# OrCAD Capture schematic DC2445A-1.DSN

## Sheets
1 PAGE 2: size Custom; title: BAR GRAPH FOR 400mA WIRELESS SYNCHRONOUS; rev: 1; note: DEMO CIRCUIT 2445A - A / B
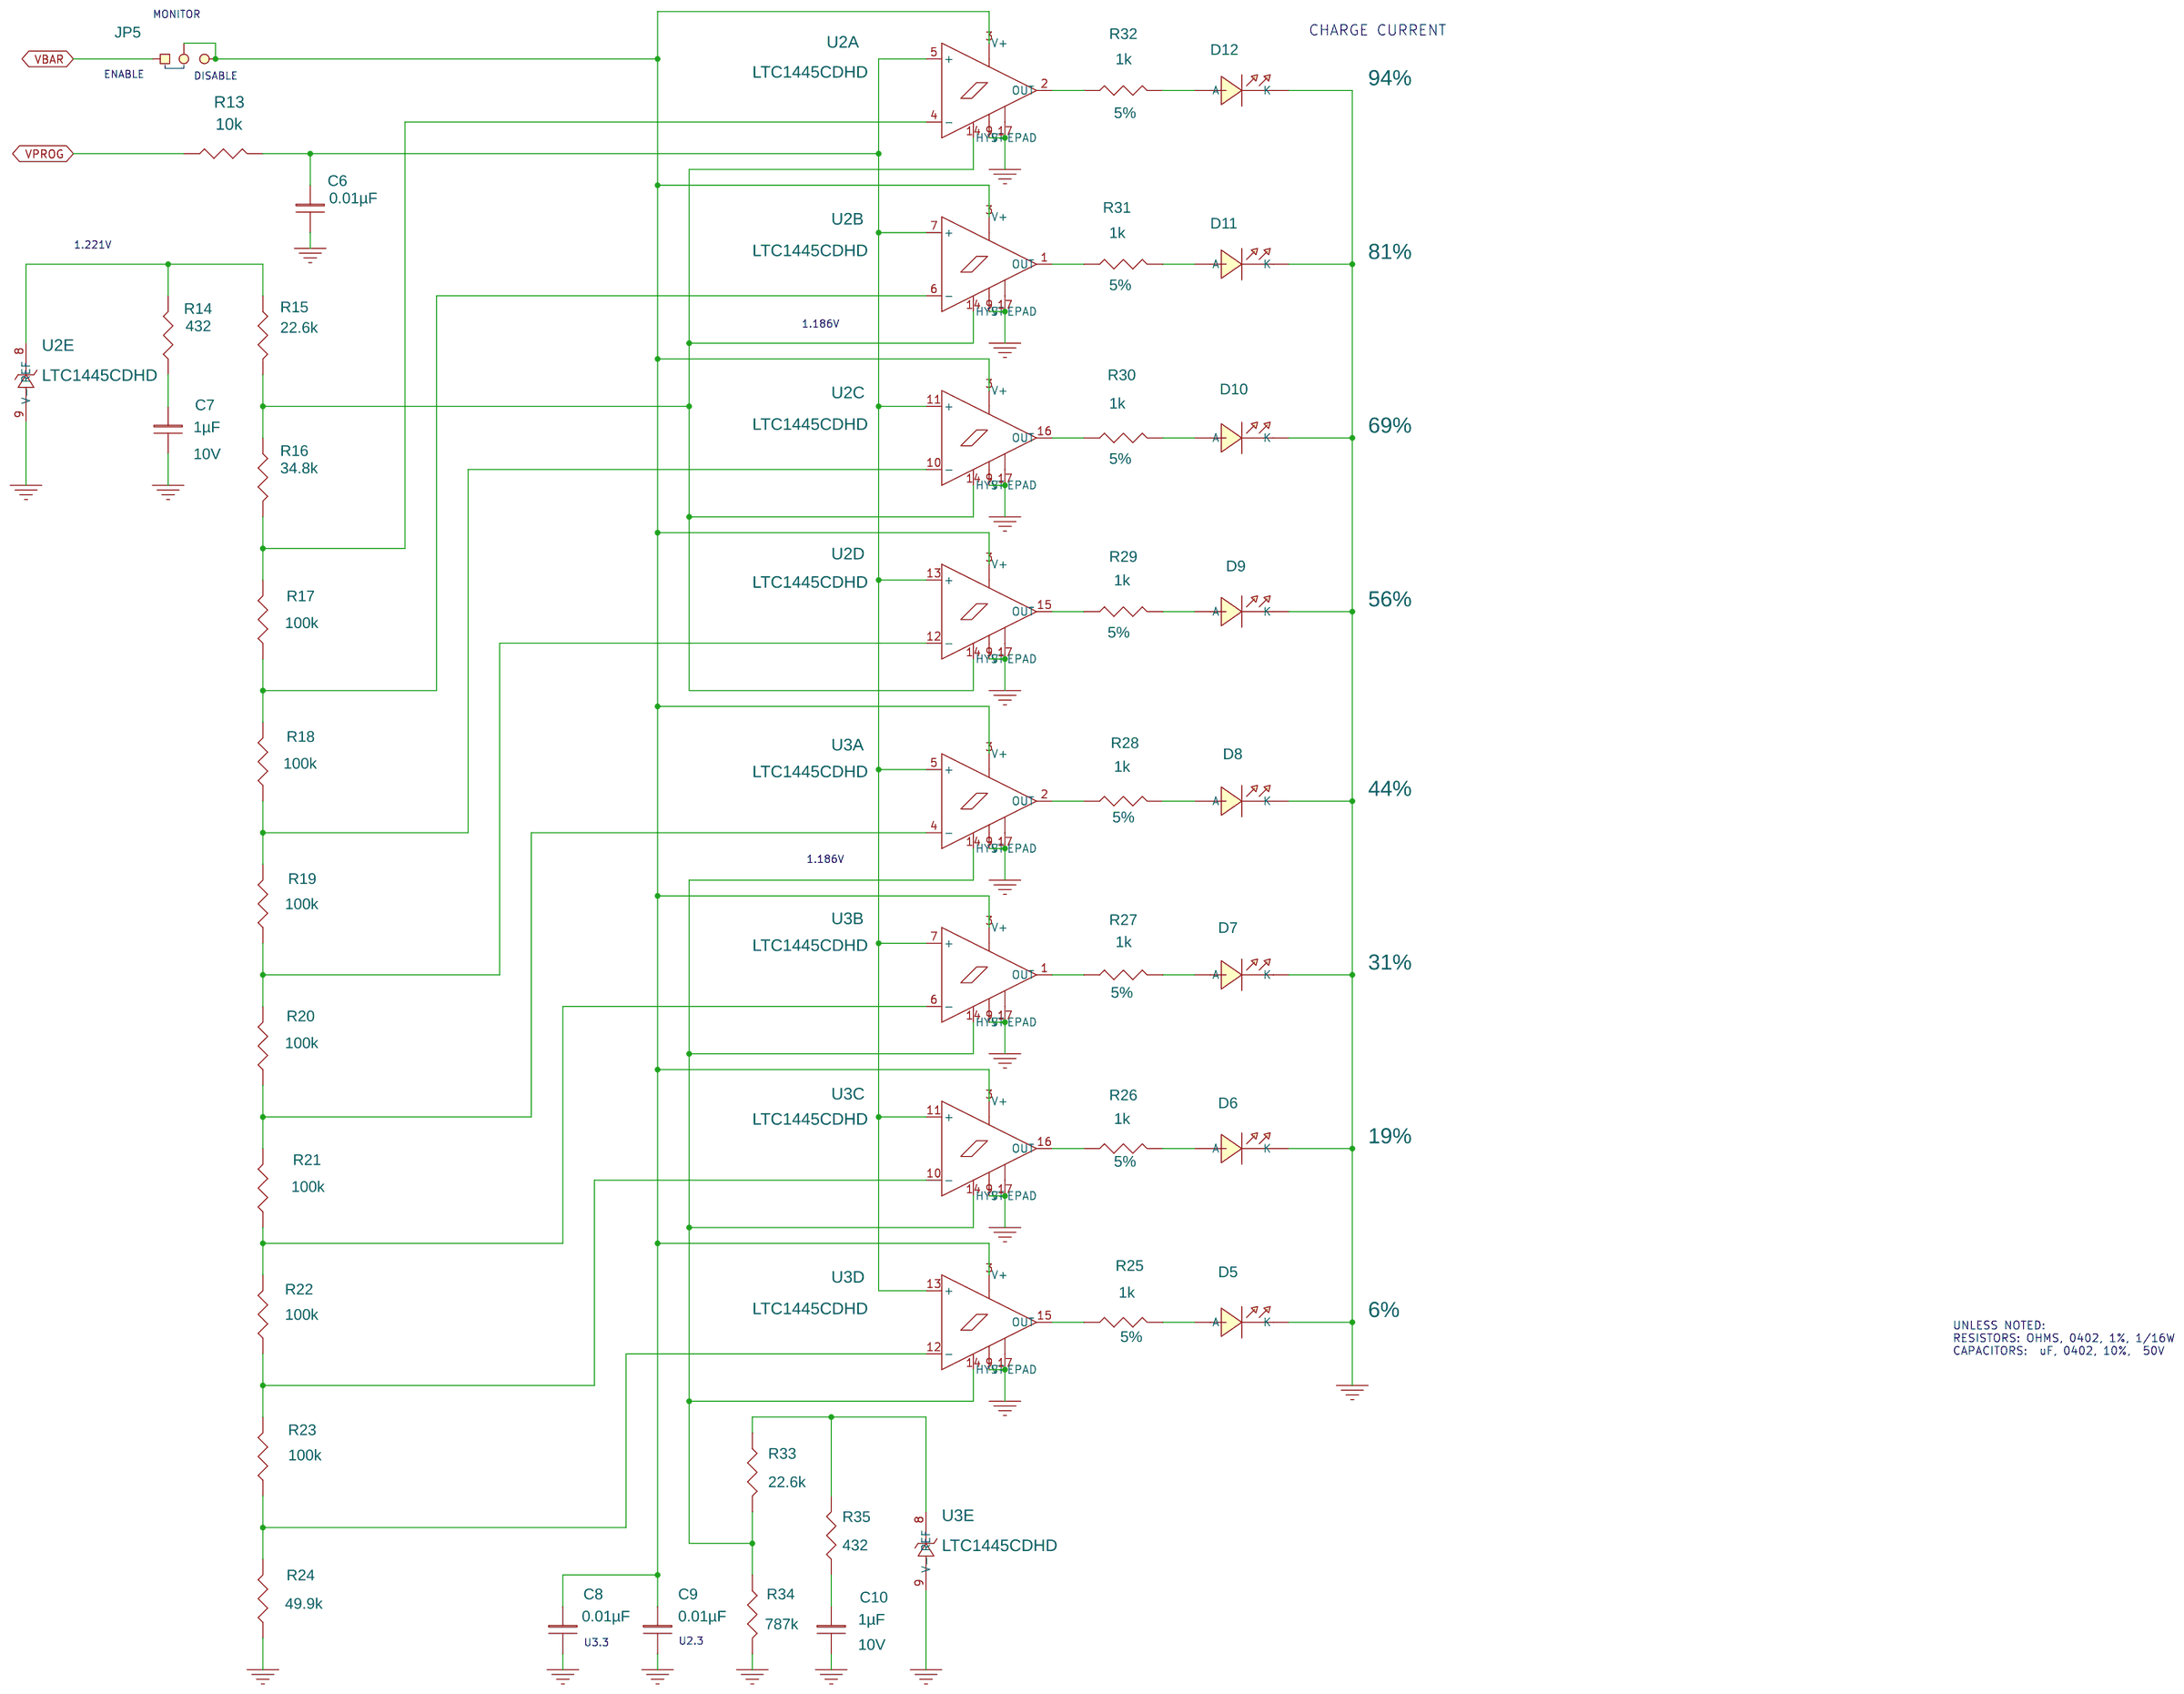
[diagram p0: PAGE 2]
2 PAGE 1: size A; title: 400mA WIRELESS SYNCHRONOUS BUCK BATTERY CHARGER
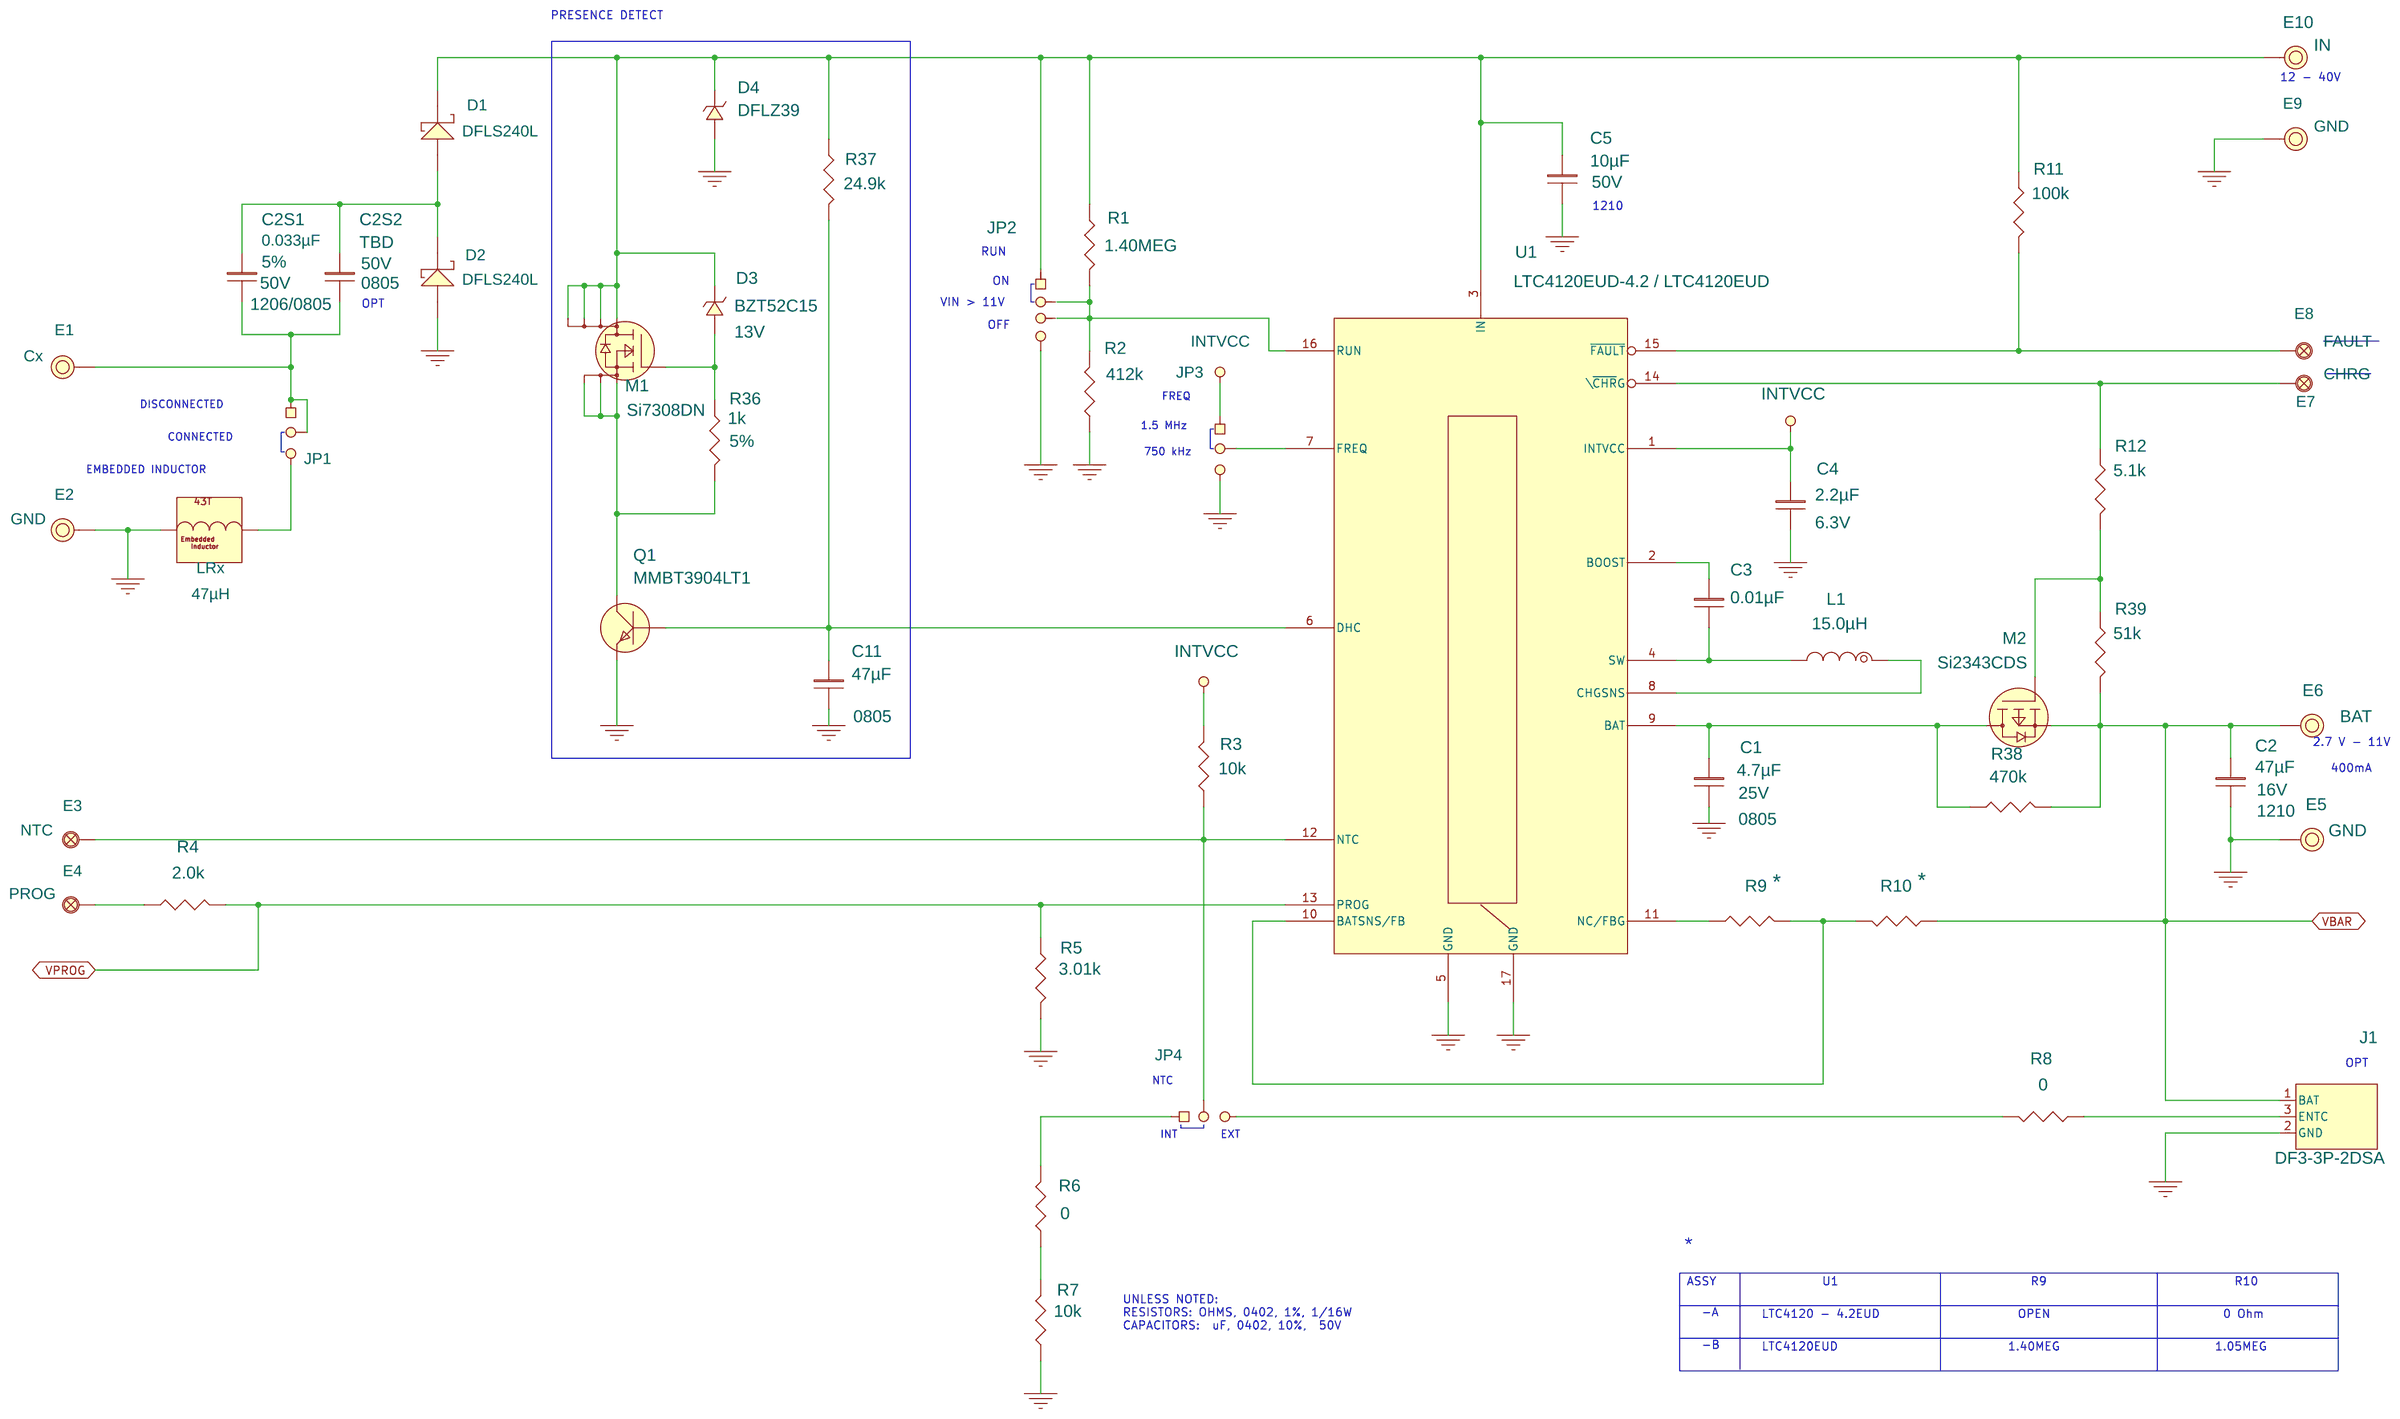
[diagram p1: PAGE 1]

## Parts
sheet PAGE 1
C1  4.7µF  [0805]
C2  47µF  [1210]
C2S1  0.033µF  [1206/0805]
C2S2  TBD  [0805]
C3  0.01µF  [0402-small]
C4  2.2µF  [0402-SMALL]
C5  10µF  [1210]
C11  47µF  [0805]
D1  DFLS240L  [POWERDI123A]
D2  DFLS240L  [POWERDI123A]
D3  BZT52C15  [DIODES-INC-SOD523]
D4  DFLZ39  [POWERDI123A]
E1  Cx  [MILL-MAX-2501-2]
E2  GND  [MILL-MAX-2501-2]
E3  NTC  [MILL-MAX-2308]
E4  PROG  [MILL-MAX-2308]
E5  GND  [MILL-MAX-2501-2]
E6  BAT  [MILL-MAX-2501-2]
E7  CHRG  [MILL-MAX-2308]
E8  FAULT  [MILL-MAX-2308]
E9  GND  [MILL-MAX-2501-2]
E10  IN  [MILL-MAX-2501-2]
J1  DF3-3P-2DSA  [DF32DSHEADER]
JP1  3 PINS, 2mm  [2MMJUMP3]
JP2  4 pin jumper  [2MMJUMP4]
JP3  3 PINS, 2mm  [2MMJUMP3]
JP4  3 PINS, 2mm  [2MMJUMP3]
L1  15.0µH  [LPS4018]
LRx  47µH  [EMBEDDED_COIL]
M1  Si7308DN  [POWERPAK1212-8S]
M2  Si2343CDS  [SOT-23F]
Q1  MMBT3904LT1  [SOT-23]
R1  1.40MEG  [0402-SMALL]
R2  412k  [0402-SMALL]
R3  10k  [0402-SMALL]
R4  2.0k  [0402-SMALL]
R5  3.01k  [0402-SMALL]
R6  0  [0402-SMALL]
R7  10k  [0402-SMALL]
R8  0  [0402-SMALL]
R9  *  [0402-SMALL]
R10  *  [0402-SMALL]
R11  100k  [0402-SMALL]
R12  5.1k  [0402-SMALL]
R36  1k  [0402-SMALL]
R37  24.9k  [0402-SMALL]
R38  470k  [0402-SMALL]
R39  51k  [0402-SMALL]
U1  LTC4120EUD-4.2 / LTC4120EUD  [QFN(16)(UD)3MMX3MM]
sheet PAGE 2
C6  0.01µF  [0402-SMALL]
C7  1µF  [0402-SMALL]
C8  0.01µF  [0402-SMALL]
C9  0.01µF  [0402-SMALL]
C10  1µF  [0402-SMALL]
D5  6%  [LITE-ON-GREEN-LED]
D6  19%  [LITE-ON-GREEN-LED]
D7  31%  [LITE-ON-GREEN-LED]
D8  44%  [LITE-ON-GREEN-LED]
D9  56%  [LITE-ON-GREEN-LED]
D10  69%  [LITE-ON-GREEN-LED]
D11  81%  [LITE-ON-GREEN-LED]
D12  94%  [LITE-ON-GREEN-LED]
JP5  3 PINS, 2mm  [2MMJUMP3]
R13  10k  [0402-SMALL]
R14  432  [0402-SMALL]
R15  22.6k  [0402-SMALL]
R16  34.8k  [0402-SMALL]
R17  100k  [0402-SMALL]
R18  100k  [0402-SMALL]
R19  100k  [0402-SMALL]
R20  100k  [0402-SMALL]
R21  100k  [0402-SMALL]
R22  100k  [0402-SMALL]
R23  100k  [0402-SMALL]
R24  49.9k  [0402-SMALL]
R25  1k  [0402-SMALL]
R26  1k  [0402-SMALL]
R27  1k  [0402-SMALL]
R28  1k  [0402-SMALL]
R29  1k  [0402-SMALL]
R30  1k  [0402-SMALL]
R31  1k  [0402-SMALL]
R32  1k  [0402-SMALL]
R33  22.6k  [0402-SMALL]
R34  787k  [0402-SMALL]
R35  432  [0402-SMALL]
U2  LTC1445CDHD  [DFN(16)(DHD)5MMX4MM]  (sections A,B,C,D,E)
U3  LTC1445CDHD  [DFN(16)(DHD)5MMX4MM]  (sections A,B,C,D,E)

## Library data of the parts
C1 = C2012X5R1A106K: VOLTAGE: 25V
C2 = GRM32ER61C476KE15L: VOLTAGE: 16V
C2S1 = GRM31CR61E106KA12L: PART: GRM21B5C1H223JA01L; Tolerance: 5%; VOLTAGE: 50V
C2S2 = GRM31CR61E106KA12L: PART: GRM2165C1H472JA01D; Tolerance: 5%; VOLTAGE: 50V
C3 = VJ0402Y103JXXA_1
C4 = GRM155R60J225ME15D: VOLTAGE: 6.3V
C5 = GRM31CR61E106KA12L: 6th Part Field: CL31A106KBHNNNB; VOLTAGE: 50V
C11 = GRM31CR60J107ME39L
D1 D2 = DFLS1100_0
D3 = DFLZ39: VZ: 13V
D4 = DFLZ39
E1 E2 E5 E9 E10 = E_3
E3 E4 E7 E8 = TP_KEY_1502-2_0: 4th Part Field: MILL-MAX; 5th Part Field: 2308-2; 7th Part Field: TURRET, SIGNAL; 9th Part Field: EN1; Part Number: MILL-MAX 2308-2
E6 = E_3: TURRET
J1 = CON3_2
JP1 JP3-JP5 = JP3X1_079_NO_6: 4TH PART FIELD: SAMTEC; 5TH PART FIELD: TMM-103-02-L-S; 7TH PART FIELD: HEADER; Part Number: TMM-103-02-L-S
JP2 = 2MMX2MM4PIN_1: Critical: F; MPN: TMM-104-02-L-S; Manufacturer: SAM; Populate: T; Size: 2mm
L1 = LPS4018-153MLC
LRx = LPS4018-153MLC_1
M1 = Si4108DY
M2 = Si2343DS
Q1 = MMBT3904LT1G_1
R1 = CRCW0402140KFKED
R2 R9 R10 R14 R17-R24 R35 = CRCW0402100KFKED
R3 = CR16-103JM_0: 2nd Part Field: 0402; 3rd Part Field: CHIP; 4th Part Field: VISHAY; 5th Part Field: CRCW040210K0FKED; 7th Part Field: RES; Part Number: VISHAY CRCW0402 10K 1%; Tolerance: 1%
R4 R6 R8 R13 = CRCW04022K00JNED
R5 = CRCW04023K01FKED
R7 = CR16-103JM_0: 1st Part Field: 1/16W; 2nd Part Field: 0402; 3rd Part Field: CHIP; 4th Part Field: VISHAY; 5th Part Field: CRCW040210K0FKED; 7th Part Field: RES; Part Number: VISHAY CRCW0402 10k 1%; Tolerance: 1%
R11 R12 R38 R39 = CRCW0402100KJNED
R36 = CRCW0402140KFKED: TOLERANCE: 5%
R37 = CRCW040222K0JNED: TOLERANCE: 1%
U1 = 20LQFN(3X3)_99
C6 C8 C9 = GRM31CR61E106KA12L
C7 C10 = GRM31CR61E106KA12L: VOLTAGE: 10V
D5-D12 = ln1351-c-tr_1: 5th Part Field: LNJ336W83RA; 9th Part Field: SMT, GREEN; Part Number: LNJ336W83RA
R15 R33 = CRCW040222K6FKED
R16 = CRCW040227K4FKED
R25-R32 = CRCW0402100KFKED: Tolerance: 5%
R34 = CRCW0402787KFKED
U2 U3 = LTC1445CDHD_7

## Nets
GND: C1.2 C2.2 C4.2 C5.2 C6.2 C7.2 C8.2 C9.2 C10.2 C11.2 D2.2(A) D4.2 D5.2(K) D6.2(K) D7.2(K) D8.2(K) D9.2(K) D10.2(K) D11.2(K) D12.2(K) E2.1(A) E5.1(A) E9.1(A) J1.2(GND) JP2.4 JP3.3 LRx.2 Q1.2(E) R2.1(pin1) R5.2(pin2) R7.2 R24.1(pin1) R34.2(pin2) U1.5(GND) U1.17(GND) U2.9(V-) U2.17(EPAD) U3.9(V-) U3.17(EPAD)
INTVCC: C4.1 JP3.1 R3.1 U1.1(INTVCC)
VBAR: C2.1 E6.1(A) J1.1(BAT) JP5.1 M2.2(S) R10.1(pin1) R38.2(pin2) R39.2(pin2)
VPROG: R4.2(pin2) R5.1(pin1) R13.1(pin1) U1.13(PROG)
N17141032: JP2.2 JP2.3 R1.2(pin2) R2.2(pin2) U1.16(RUN)
N17265375: R6.1(pin1) R7.1
N17301488: E3.1 JP4.2 R3.2 U1.12(NTC)
N17334729: C5.1 D1.1(C) D3.1 D4.1 E10.1(A) JP2.1 M1.5(D) M1.6(Dtab) M1.7(Dtab1) M1.8(Dtab2) R1.1(pin1) R11.1(pin1) R37.1(pin1) U1.3(IN)
N17342929: C3.2 L1.2 U1.4(SW)
N17342957: L1.1 U1.8(CHGSNS)
N17343033: C3.1 U1.2(BOOST)
N17343389: E7.1 R12.1(pin1) U1.14(\~{CHR}G)
N17343421: E8.1 R11.2(pin2) U1.15(~{FAULT})
N17345301: E4.1 R4.1(pin1)
N17348152: C2S1.1 C2S2.1 D1.2(A) D2.1(C)
N17350124: R9.1(pin1) U1.11(NC/FBG)
N17352615: R9.2(pin2) R10.2(pin2) U1.10(BATSNS/FB)
N17379047: C6.1 R13.2(pin2) U2.5(+) U2.7(+) U2.11(+) U2.13(+) U3.5(+) U3.7(+) U3.11(+) U3.13(+)
N17387943: R33.2(pin2) R34.1(pin1) U3.14(HYST)
N17388008: R15.2(pin2) R16.1(pin1) U2.14(HYST)
N17388100: C8.1 C9.1 JP5.2 JP5.3 U2.3(V+) U3.3(V+)
N17388523: R16.2(pin2) R17.2(pin2) U2.4(-)
N17388537: R17.1(pin1) R18.2(pin2) U2.6(-)
N17388551: R18.1(pin1) R19.2(pin2) U2.10(-)
N17388565: R19.1(pin1) R20.2(pin2) U2.12(-)
N17388579: R20.1(pin1) R21.2(pin2) U3.4(-)
N17388621: R23.1(pin1) R24.2(pin2) U3.12(-)
N17389104: R14.2(pin2) R15.1(pin1) U2.8(REF)
N17396884: R32.1(pin1) U2.2(OUT)
N17396885: R28.1(pin1) U3.2(OUT)
N17396886: R29.1(pin1) U2.15(OUT)
N17396887: R31.1(pin1) U2.1(OUT)
N17396889: R30.1(pin1) U2.16(OUT)
N17396890: R25.1(pin1) U3.15(OUT)
N17396891: R27.1(pin1) U3.1(OUT)
N17397508: R22.1(pin1) R23.2(pin2) U3.10(-)
N17397664: R21.1(pin1) R22.2(pin2) U3.6(-)
N17400203: C7.1 R14.1(pin1)
N17419772: D12.1(A) R32.2(pin2)
N17419787: D11.1(A) R31.2(pin2)
N17419802: D10.1(A) R30.2(pin2)
N17419817: D9.1(A) R29.2(pin2)
N17419832: D8.1(A) R28.2(pin2)
N17419847: D7.1(A) R27.2(pin2)
N17419862: D6.1(A) R26.2(pin2)
N17419877: D5.1(A) R25.2(pin2)
N17423487: R26.1(pin1) U3.16(OUT)
N17431016: R33.1(pin1) R35.2(pin2) U3.8(REF)
N17431455: C10.1 R35.1(pin1)
N17489523: C1.1 M2.3(D) R38.1(pin1) U1.9(BAT)
N17519145: JP4.3 R8.2(pin2)
N17579808: M2.1(G) R12.2(pin2) R39.1(pin1)
N17587239: C2S1.2 C2S2.2 E1.1(A) JP1.1 JP1.2
N17588546: M1.1(S) M1.2(Stab) M1.3(Stab1) Q1.3(C) R36.2(pin2)
N17588573: C11.1 Q1.1(B) R37.2(pin2) U1.6(DHC)
N17596253: JP1.3 LRx.1
N17596910: D3.2 M1.4(G) R36.1(pin1)
N17598615: JP3.2 U1.7(FREQ)
N17600692: JP4.1 R6.2(pin2)
N17601247: J1.3(ENTC) R8.1(pin1)

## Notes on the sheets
sheet 1
- MONITOR
- CHARGE CURRENT
- ENABLE
- DISABLE
- 1.221V
- 1.186V
- 1.186V
- UNLESS NOTED:
  RESISTORS: OHMS, 0402, 1%, 1/16W
  CAPACITORS:  uF, 0402, 10%,  50V
- U3.3
- U2.3
sheet 2
- PRESENCE DETECT
- 12 - 40V
- 1210
- RUN
- ON
- OPT
- VIN > 11V
- OFF
- DISCONNECTED
- FREQ
- CONNECTED
- 1.5 MHz
- 750 kHz
- EMBEDDED INDUCTOR
- 2.7 V - 11V
- 400mA
- OPT
- NTC
- INT
- EXT
- *
- ASSY
- U1
- R9
- R10
- UNLESS NOTED:
  RESISTORS: OHMS, 0402, 1%, 1/16W
  CAPACITORS:  uF, 0402, 10%,  50V
- -A
- LTC4120 - 4.2EUD
- OPEN
- 0 Ohm
- -B
- LTC4120EUD
- 1.40MEG
- 1.05MEG
